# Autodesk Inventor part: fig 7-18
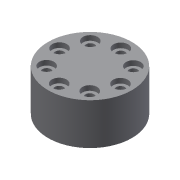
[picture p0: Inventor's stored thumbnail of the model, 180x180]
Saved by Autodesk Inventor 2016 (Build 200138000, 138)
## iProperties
Created: 2004-05
Part Number: fig 7-18
Document SubType Name: Modeling
Designer: CADCIM Technologies
Manufacturer: Standard
Standards Organization: Custom
Density: 1 g/cm^3
Material: Generic
Appearance: Default
Author: CADCIM Technologies
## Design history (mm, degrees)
sketch "Sketch1"
  geometry: C1 r 17.175 at (0, 0)
  constraints: 1 centre point
extrude "Extrusion1" new body sketch "Sketch1" distance "d0" = 17; taper "d1" = 0 deg
sketch "Sketch2"
  geometry: 1 further point
hole "Hole1" sketch "Sketch2" at (12.571, -0.074) diameter "d2" = 3.5; stored, may be unused: countersink angle "d6" = 90 deg, drill point angle "d8" = 118 deg; dims "d3" = 6, "d4" = 6, "d5" = 2, "d7" = 8
pattern_circular "Circular Pattern1" dims angle "d11" = 360 deg
body "Solid1"
